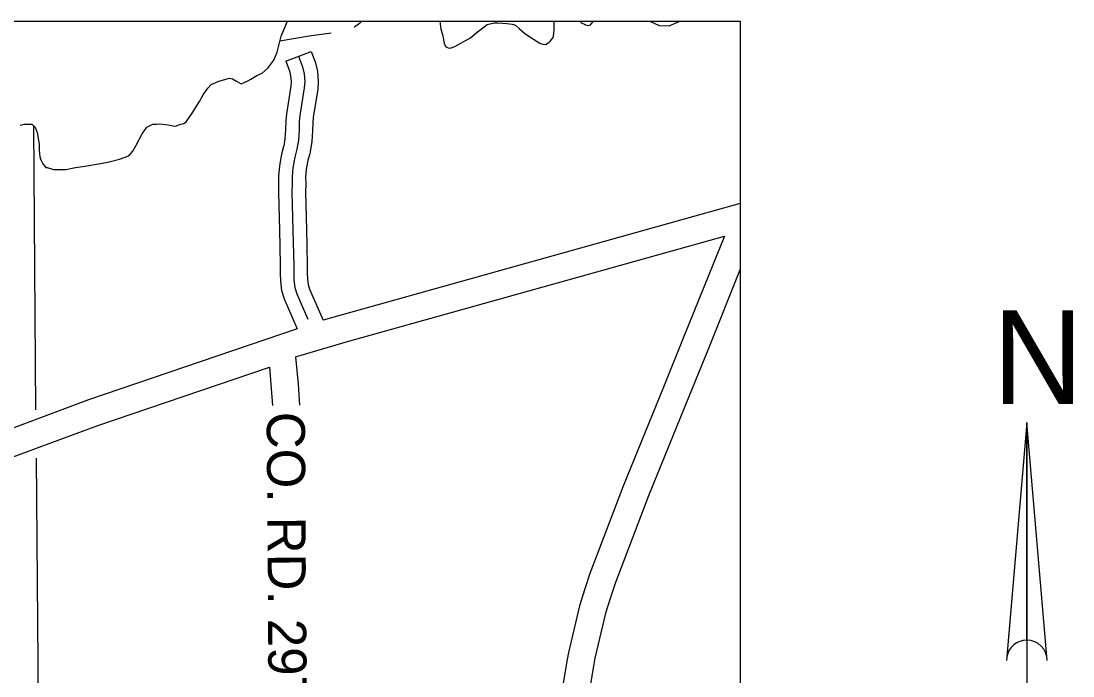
# Model space of a CAD drawing. Extents: x 1373094 to 1376427, y 1168361 to 1170494.
# Drawn here: x 1375231.7 to 1375619.6, y 1169292.6 to 1169534.2 of the extents above; entities that cross this region are included whole.
import ezdxf

# ---------------------------------------------------------------- set-up
doc = ezdxf.new("R2010")
doc.units = 0
for name, color, linetype in [('R_Axis', 7, 'Continuous'), ('R_Draft', 7, 'Continuous'), ('R_No Plot', 7, 'Continuous'), ('R_Water Annot', 7, 'Continuous')]:
    doc.layers.add(name, color=color, linetype=linetype)

msp = doc.modelspace()

# ---------------------------------------------------------------- linework, layer by layer
at = {"layer": 'R_Axis'}
msp.add_line((1375329.32, 1169519.41), (1375338.69, 1169522.91), dxfattribs=at)
for points in [[(1375312.89, 1169510.96), (1375313.95, 1169511.5), (1375315.28, 1169512.05), (1375316.47, 1169512.72), (1375318.59, 1169514.07), (1375320.57, 1169514.88), (1375322.69, 1169516.76), (1375324.93, 1169519.71), (1375326.11, 1169522.66), (1375327.66, 1169528.54), (1375329.91, 1169534.16)], [(1375312.89, 1169510.96), (1375313.95, 1169511.5), (1375315.28, 1169512.05), (1375316.47, 1169512.72), (1375318.59, 1169514.07), (1375320.57, 1169514.88), (1375322.69, 1169516.76), (1375324.93, 1169519.71), (1375326.11, 1169522.66), (1375327.66, 1169528.54), (1375329.91, 1169534.16)], [(1375357.31, 1169534.16), (1375356.47, 1169533.3), (1375354.63, 1169531.95), (1375354.49, 1169531.9)], [(1375386.13, 1169534.16), (1375386.54, 1169531.15), (1375386.95, 1169529.55), (1375387.22, 1169528.75), (1375387.49, 1169527.28), (1375387.77, 1169525.95), (1375388.18, 1169524.75), (1375389.24, 1169524.22), (1375389.91, 1169524.09), (1375391.63, 1169524.77), (1375394.94, 1169526.66), (1375397.46, 1169528.01), (1375399.31, 1169529.62), (1375403.54, 1169532.85), (1375406.2, 1169533.53), (1375407.53, 1169533.54), (1375409.26, 1169533.42), (1375410.85, 1169533.29), (1375412.85, 1169533.04), (1375414.05, 1169532.64), (1375415.38, 1169531.45), (1375417.39, 1169529.73), (1375419.66, 1169528.14), (1375423, 1169526.02), (1375424.06, 1169525.63), (1375425.26, 1169525.5), (1375426.45, 1169526.31), (1375426.98, 1169526.85), (1375427.9, 1169528.05), (1375428.16, 1169529.39), (1375428.28, 1169531.13), (1375428.26, 1169533.93), (1375428.26, 1169534.16)], [(1375386.13, 1169534.16), (1375386.54, 1169531.15), (1375386.95, 1169529.55), (1375387.22, 1169528.75), (1375387.49, 1169527.28), (1375387.77, 1169525.95), (1375388.18, 1169524.75), (1375389.24, 1169524.22), (1375389.91, 1169524.09), (1375391.63, 1169524.77), (1375394.94, 1169526.66), (1375397.46, 1169528.01), (1375399.31, 1169529.62), (1375403.54, 1169532.85), (1375406.2, 1169533.53), (1375407.53, 1169533.54), (1375409.26, 1169533.42), (1375410.85, 1169533.29), (1375412.85, 1169533.04), (1375414.05, 1169532.64), (1375415.38, 1169531.45), (1375417.39, 1169529.73), (1375419.66, 1169528.14), (1375423, 1169526.02), (1375424.06, 1169525.63), (1375425.26, 1169525.5), (1375426.45, 1169526.31), (1375426.98, 1169526.85), (1375427.9, 1169528.05), (1375428.16, 1169529.39), (1375428.28, 1169531.13), (1375428.26, 1169533.93), (1375428.26, 1169534.16)], [(1375437.97, 1169534.16), (1375438.24, 1169533.45), (1375439.44, 1169533.06), (1375439.84, 1169532.79), (1375441.04, 1169532.53), (1375441.7, 1169532.81), (1375442.62, 1169534.01), (1375442.7, 1169534.16)], [(1375437.97, 1169534.16), (1375438.24, 1169533.45), (1375439.44, 1169533.06), (1375439.84, 1169532.79), (1375441.04, 1169532.53), (1375441.7, 1169532.81), (1375442.62, 1169534.01), (1375442.7, 1169534.16)], [(1375463.59, 1169534.16), (1375463.62, 1169534.13), (1375466.96, 1169532.55)], [(1375463.59, 1169534.16), (1375463.62, 1169534.13), (1375466.96, 1169532.55)], [(1375466.96, 1169532.55), (1375470.68, 1169532.44), (1375474.39, 1169533.93), (1375474.78, 1169534.16)], [(1375466.96, 1169532.55), (1375470.68, 1169532.44), (1375474.39, 1169533.93), (1375474.78, 1169534.16)], [(1375346, 1169529.71), (1375337.9, 1169528.52), (1375327.17, 1169526.69)], [(1375338.69, 1169522.91), (1375340.27, 1169518.68), (1375340.99, 1169515.49), (1375341.3, 1169511.89), (1375341.1, 1169509.01), (1375339.47, 1169498.62), (1375339.27, 1169496.67), (1375339.19, 1169493.71), (1375338.97, 1169489.66), (1375338.34, 1169485.89), (1375338.16, 1169485.21)], [(1375329.32, 1169519.41), (1375330.66, 1169515.81), (1375331.09, 1169513.94), (1375331.27, 1169511.81), (1375331.16, 1169510.14), (1375329.54, 1169499.9), (1375329.28, 1169497.3), (1375329.2, 1169494.11), (1375329.02, 1169490.76), (1375328.56, 1169488.02), (1375328.5, 1169487.82)], [(1375334, 1169521.16), (1375335.47, 1169517.24), (1375336.04, 1169514.72), (1375336.29, 1169511.85), (1375336.13, 1169509.57), (1375334.5, 1169499.26), (1375334.28, 1169496.99), (1375334.2, 1169493.91), (1375334, 1169490.21), (1375333.45, 1169486.95), (1375332.63, 1169483.93), (1375331.91, 1169480.05), (1375331.63, 1169476.7), (1375331.67, 1169474.17), (1375331.59, 1169471.03), (1375331.96, 1169457), (1375332.25, 1169443.65), (1375332.23, 1169440.98), (1375332.33, 1169438.71), (1375332.65, 1169435.84), (1375333.42, 1169433.51), (1375337.43, 1169424.18)], [(1375231.36, 1169495.8), (1375232.82, 1169496.08), (1375234.42, 1169496.09), (1375235.62, 1169496.1), (1375236.95, 1169495.04), (1375237.63, 1169493.04), (1375237.91, 1169491.7), (1375238.33, 1169488.64), (1375238.34, 1169486.5), (1375238.62, 1169484.1), (1375239.03, 1169482.9), (1375239.7, 1169481.43), (1375240.78, 1169480.11), (1375241.31, 1169480.11), (1375243.71, 1169479.45), (1375248.23, 1169479.35), (1375251.81, 1169480.17), (1375255.26, 1169480.59), (1375260.97, 1169481.56), (1375264.16, 1169482.24), (1375268.01, 1169483.2), (1375271.46, 1169484.42), (1375272.91, 1169486.17), (1375273.96, 1169488.17), (1375276.32, 1169492.59), (1375278.03, 1169495.01), (1375280.29, 1169496.09), (1375281.75, 1169496.1), (1375282.81, 1169496.24), (1375284.94, 1169495.98), (1375286.54, 1169495.72), (1375288.27, 1169495.33), (1375289.06, 1169495.47), (1375290.12, 1169496.01), (1375291.72, 1169496.42), (1375292.64, 1169496.96), (1375294.75, 1169500.18), (1375297.51, 1169504.47), (1375298.83, 1169506.88), (1375300.54, 1169509.42), (1375301.86, 1169510.77), (1375304.64, 1169511.98), (1375306.9, 1169512.53), (1375308.49, 1169513.07), (1375309.69, 1169512.81), (1375311.15, 1169512.02), (1375312.89, 1169510.96)], [(1375231.36, 1169495.8), (1375232.82, 1169496.08), (1375234.42, 1169496.09), (1375235.62, 1169496.1), (1375236.95, 1169495.04), (1375237.63, 1169493.04), (1375237.91, 1169491.7), (1375238.33, 1169488.64), (1375238.34, 1169486.5), (1375238.62, 1169484.1), (1375239.03, 1169482.9), (1375239.7, 1169481.43), (1375240.78, 1169480.11), (1375241.31, 1169480.11), (1375243.71, 1169479.45), (1375248.23, 1169479.35), (1375251.81, 1169480.17), (1375255.26, 1169480.59), (1375260.97, 1169481.56), (1375264.16, 1169482.24), (1375268.01, 1169483.2), (1375271.46, 1169484.42), (1375272.91, 1169486.17), (1375273.96, 1169488.17), (1375276.32, 1169492.59), (1375278.03, 1169495.01), (1375280.29, 1169496.09), (1375281.75, 1169496.1), (1375282.81, 1169496.24), (1375284.94, 1169495.98), (1375286.54, 1169495.72), (1375288.27, 1169495.33), (1375289.06, 1169495.47), (1375290.12, 1169496.01), (1375291.72, 1169496.42), (1375292.64, 1169496.96), (1375294.75, 1169500.18), (1375297.51, 1169504.47), (1375298.83, 1169506.88), (1375300.54, 1169509.42), (1375301.86, 1169510.77), (1375304.64, 1169511.98), (1375306.9, 1169512.53), (1375308.49, 1169513.07), (1375309.69, 1169512.81), (1375311.15, 1169512.02), (1375312.89, 1169510.96)], [(1375236.23, 1169495.61), (1375237.07, 1169390.67)], [(1375328.5, 1169487.82), (1375327.75, 1169485.04), (1375326.95, 1169480.72), (1375326.62, 1169476.88), (1375326.67, 1169474.19), (1375326.59, 1169471.02), (1375326.96, 1169456.88), (1375327.08, 1169451.38)], [(1375338.16, 1169485.21), (1375337.51, 1169482.83), (1375336.87, 1169479.38), (1375336.63, 1169476.53), (1375336.67, 1169474.15), (1375336.59, 1169471.03), (1375336.96, 1169457.12), (1375337.08, 1169451.6)], [(1375496.95, 1169466.89), (1375343.05, 1169423.75)], [(1375332.89, 1169410.24), (1375352.06, 1169415.89), (1375491.07, 1169454.85)], [(1375491.07, 1169454.85), (1375475.9, 1169417.11), (1375468.56, 1169399.1), (1375453.78, 1169362.61), (1375441.48, 1169330.39), (1375439.61, 1169324.64), (1375437.58, 1169318.47), (1375433.53, 1169301.17), (1375433.08, 1169298.67), (1375425.81, 1169255.31), (1375425.06, 1169250.04)], [(1375327.08, 1169451.38), (1375327.25, 1169443.61), (1375327.23, 1169440.88), (1375327.35, 1169438.32), (1375327.74, 1169434.77), (1375328.74, 1169431.74), (1375333.54, 1169420.56)], [(1375337.08, 1169451.6), (1375337.25, 1169443.68), (1375337.23, 1169441.07), (1375337.32, 1169439.1), (1375337.56, 1169436.91), (1375338.1, 1169435.29), (1375343.05, 1169423.75)], [(1375496.95, 1169442.66), (1375485.17, 1169413.36), (1375477.82, 1169395.33), (1375463.09, 1169358.95), (1375450.91, 1169327.06), (1375449.11, 1169321.54), (1375447.22, 1169315.76), (1375443.32, 1169299.13), (1375442.93, 1169296.95), (1375435.69, 1169253.77), (1375434.89, 1169248.2)], [(1375333.54, 1169420.56), (1375256.62, 1169394.37), (1375225.05, 1169382.65), (1375195.38, 1169372.11), (1375096.71, 1169337.09)], [(1375332.89, 1169410.24), (1375333.85, 1169400.2), (1375334.42, 1169392.48)], [(1375094.71, 1169325.77), (1375198.72, 1169362.68), (1375228.46, 1169373.25), (1375259.98, 1169384.95), (1375323.36, 1169406.53)], [(1375323.36, 1169406.53), (1375324.4, 1169392.3)], [(1375237.22, 1169372.94), (1375238.19, 1169252.01), (1375240.86, 1168901.02)]]:
    msp.add_lwpolyline(points, dxfattribs=at)
at = {"layer": 'R_Draft'}
for p, q in [((1375602.62, 1169386.03), (1375595.23, 1169299.56)), ((1375602.62, 1169386.03), (1375602.62, 1169267.6)), ((1375602.62, 1169305.78), (1375602.62, 1169386.03)), ((1375595.33, 1169300.76), (1375595.67, 1169301.1)), ((1375595.37, 1169301.23), (1375596.05, 1169301.91))]:
    msp.add_line(p, q, dxfattribs=at)
msp.add_lwpolyline([(1375610.12, 1169298.28), (1375602.62, 1169386.03), (1375595.12, 1169298.28)], dxfattribs=at)
for start, end in [(0, 180), (90, 170.2296)]:
    msp.add_arc((1375602.62, 1169298.28), 7.5, start, end, dxfattribs=at)
at = {"layer": 'R_No Plot'}
msp.add_lwpolyline([(1373989.53, 1169534.16), (1375496.95, 1169534.16), (1375496.95, 1168608.52), (1373989.53, 1168608.52)], close=True, dxfattribs=at)

# ---------------------------------------------------------------- texts
at = {"layer": 'R_Draft'}
msp.add_text('N', height=34.62, dxfattribs=at).set_placement((1375589.97, 1169392.84))
at = {"layer": 'R_Water Annot'}
msp.add_text('CO. RD. 297', height=14.08, rotation=270.3797, dxfattribs=at).set_placement((1375322.26, 1169389.96))

doc.saveas('drawing.dxf')
